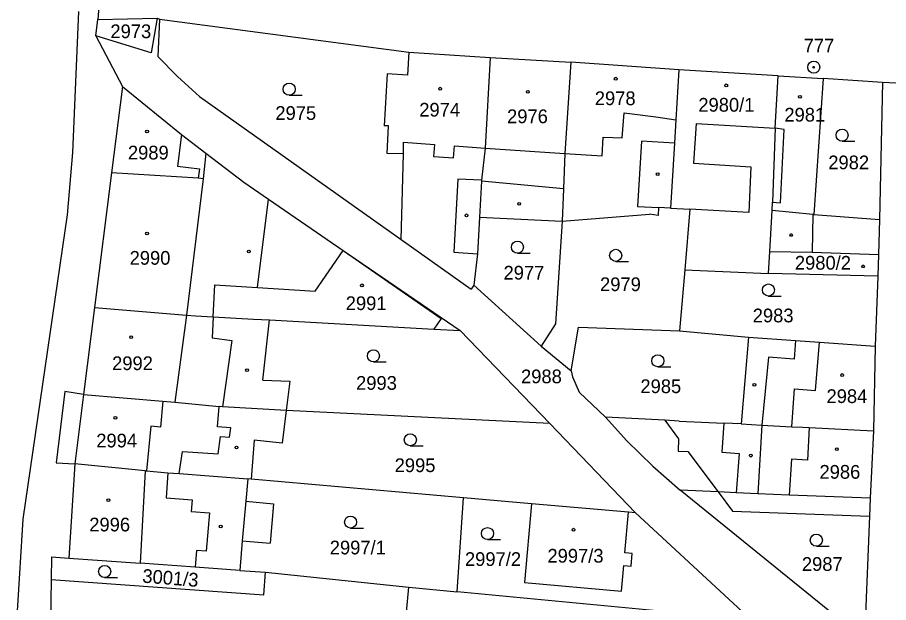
# Model space of a CAD drawing. Extents: x -755819 to -753140, y -1169796 to -1166000.
# Drawn here: x -754210.5 to -754102.6, y -1169066.6 to -1168994.1 of the extents above; entities that cross this region are included whole.
import ezdxf

# ---------------------------------------------------------------- set-up
doc = ezdxf.new("R2010")
doc.units = 0
for name, color, linetype in [('Vrstva 1', 7, 'Continuous'), ('Vrstva 17', 7, 'Continuous'), ('Vrstva 18', 7, 'Continuous'), ('Vrstva 19', 7, 'Continuous'), ('Vrstva 24', 7, 'Continuous'), ('Vrstva 25', 7, 'Continuous'), ('Vrstva 4', 7, 'Continuous')]:
    doc.layers.add(name, color=color, linetype=linetype)

msp = doc.modelspace()

# ---------------------------------------------------------------- linework, layer by layer
at = {"layer": 'Vrstva 1'}
for p, q in [((-754199.65, -1168981.56), (-754200.57, -1168994.32)), ((-754203.67, -1169010.81), (-754202.95, -1168993.33)), ((-754200.83, -1168996.33), (-754200.57, -1168994.32)), ((-754200.57, -1168994.32), (-754193.23, -1168994.15)), ((-754193.23, -1168994.15), (-754193.97, -1168998.42)), ((-754193.23, -1168994.15), (-754192.93, -1168994.25)), ((-754192.93, -1168994.25), (-754193.14, -1168998.89)), ((-754192.93, -1168994.25), (-754162.03, -1168998.34)), ((-754193.97, -1168998.42), (-754200.83, -1168996.33)), ((-754200.83, -1168996.33), (-754197.53, -1169002.63)), ((-754162.03, -1168998.34), (-754162.21, -1169001.2)), ((-754162.03, -1168998.34), (-754151.95, -1168999.03)), ((-754193.14, -1168998.89), (-754190.69, -1169001.38)), ((-754151.95, -1168999.03), (-754152.6, -1169010.26)), ((-754151.95, -1168999.03), (-754141.96, -1168999.6)), ((-754141.96, -1168999.6), (-754142.72, -1169010.93)), ((-754128.58, -1169000.55), (-754141.96, -1168999.6)), ((-754190.69, -1169001.38), (-754187.96, -1169003.85)), ((-754164.74, -1169001.06), (-754165.1, -1169007.47)), ((-754162.21, -1169001.2), (-754164.74, -1169001.06)), ((-754128.58, -1169000.55), (-754128.95, -1169006.76)), ((-754116.28, -1169001.27), (-754128.58, -1169000.55)), ((-754116.66, -1169007.79), (-754116.28, -1169001.27)), ((-754116.28, -1169001.27), (-754110.7, -1169001.6)), ((-754197.53, -1169002.63), (-754198.87, -1169013.3)), ((-754197.53, -1169002.63), (-754190.21, -1169008.55)), ((-754110.7, -1169001.6), (-754111.85, -1169018.49)), ((-754103.34, -1169002.11), (-754110.7, -1169001.6)), ((-754103.34, -1169002.11), (-754103.73, -1169019.08)), ((-754093.04, -1169002.69), (-754103.34, -1169002.11)), ((-754187.96, -1169003.85), (-754162.98, -1169021.58)), ((-754128.95, -1169006.76), (-754129.12, -1169009.63)), ((-754164.55, -1169007.5), (-754165.1, -1169007.47)), ((-754164.72, -1169010.92), (-754164.55, -1169007.5)), ((-754116.66, -1169007.79), (-754116.97, -1169016.96)), ((-754190.21, -1169008.55), (-754187.19, -1169010.87)), ((-754129.12, -1169009.63), (-754129.61, -1169017.68)), ((-754204.35, -1169018.52), (-754203.67, -1169010.81)), ((-754187.19, -1169010.87), (-754187.52, -1169014.04)), ((-754187.19, -1169010.87), (-754182.5, -1169014.48)), ((-754162.72, -1169010.97), (-754164.72, -1169010.92)), ((-754162.98, -1169021.58), (-754162.72, -1169010.97)), ((-754152.6, -1169010.26), (-754153.03, -1169014.22)), ((-754142.72, -1169010.93), (-754142.89, -1169015.28)), ((-754198.87, -1169013.3), (-754201.01, -1169029.98)), ((-754188.13, -1169013.98), (-754198.87, -1169013.3)), ((-754187.52, -1169014.04), (-754188.13, -1169013.98)), ((-754182.5, -1169014.48), (-754179.42, -1169016.59)), ((-754153.04, -1169014.33), (-754153.28, -1169018.81)), ((-754153.03, -1169014.22), (-754153.04, -1169014.33)), ((-754142.89, -1169015.28), (-754143.05, -1169019.32)), ((-754180.8, -1169027.54), (-754179.42, -1169016.59)), ((-754179.42, -1169016.59), (-754170.17, -1169022.93)), ((-754131.1, -1169017.6), (-754131.15, -1169018.59)), ((-754129.61, -1169017.68), (-754131.1, -1169017.6)), ((-754129.61, -1169017.68), (-754127.22, -1169017.81)), ((-754117.02, -1169017.96), (-754116.97, -1169016.96)), ((-754209.82, -1169056.23), (-754204.35, -1169018.52)), ((-754153.28, -1169018.81), (-754153.52, -1169023.33)), ((-754153.28, -1169018.81), (-754143.05, -1169019.32)), ((-754143.05, -1169019.32), (-754132.23, -1169018.43)), ((-754131.15, -1169018.59), (-754132.23, -1169018.43)), ((-754127.22, -1169017.81), (-754127.86, -1169025.32)), ((-754117.3, -1169023.07), (-754117.02, -1169017.96)), ((-754111.97, -1169018.48), (-754117.02, -1169017.96)), ((-754111.85, -1169018.49), (-754111.97, -1169018.48)), ((-754111.85, -1169018.49), (-754103.73, -1169019.08)), ((-754143.05, -1169019.32), (-754143.87, -1169032.04)), ((-754103.73, -1169019.08), (-754103.83, -1169023.43)), ((-754162.98, -1169021.58), (-754154.31, -1169027.72)), ((-754170.17, -1169022.93), (-754155.67, -1169032.87)), ((-754117.47, -1169025.79), (-754117.3, -1169023.07)), ((-754153.52, -1169023.33), (-754153.99, -1169027.25)), ((-754103.83, -1169023.43), (-754103.93, -1169026.12)), ((-754127.86, -1169025.32), (-754128.5, -1169032.89)), ((-754127.86, -1169025.32), (-754117.47, -1169025.79)), ((-754103.93, -1169026.12), (-754117.47, -1169025.79)), ((-754103.93, -1169026.12), (-754104.27, -1169034.81)), ((-754186.28, -1169031.15), (-754186.06, -1169027.21)), ((-754186.06, -1169027.21), (-754180.8, -1169027.54)), ((-754153.99, -1169027.25), (-754154.31, -1169027.72)), ((-754145.63, -1169034.78), (-754153.99, -1169027.25)), ((-754201.01, -1169029.98), (-754202.36, -1169040.77)), ((-754201.01, -1169029.98), (-754189.6, -1169030.97)), ((-754189.6, -1169030.97), (-754188.48, -1169031.03)), ((-754188.48, -1169031.03), (-754186.28, -1169031.15)), ((-754186.28, -1169031.15), (-754181.29, -1169031.43)), ((-754181.29, -1169031.43), (-754179.3, -1169031.54)), ((-754180.13, -1169039), (-754179.3, -1169031.54)), ((-754179.3, -1169031.54), (-754158.93, -1169032.69)), ((-754158.93, -1169032.69), (-754155.67, -1169032.87)), ((-754155.67, -1169032.87), (-754144.58, -1169044.37)), ((-754143.87, -1169032.04), (-754145.63, -1169034.78)), ((-754141.91, -1169037.85), (-754141.03, -1169032.42)), ((-754141.03, -1169032.42), (-754128.5, -1169032.89)), ((-754128.5, -1169032.89), (-754119.96, -1169033.67)), ((-754119.96, -1169033.67), (-754120.88, -1169044.43)), ((-754119.96, -1169033.67), (-754114.14, -1169034.09)), ((-754145.63, -1169034.78), (-754141.91, -1169037.85)), ((-754114.14, -1169034.09), (-754111.16, -1169034.31)), ((-754111.16, -1169034.31), (-754104.27, -1169034.81)), ((-754104.27, -1169034.81), (-754104.47, -1169045.3)), ((-754141.91, -1169037.85), (-754141.78, -1169038.59)), ((-754180.13, -1169039), (-754176.79, -1169039.13)), ((-754176.79, -1169039.13), (-754177.24, -1169042.75)), ((-754141.78, -1169038.59), (-754140.93, -1169040.5)), ((-754204.68, -1169040.4), (-754205.73, -1169049.26)), ((-754202.36, -1169040.77), (-754204.68, -1169040.4)), ((-754202.36, -1169040.77), (-754192.52, -1169041.61)), ((-754140.93, -1169040.5), (-754137.66, -1169043.58)), ((-754192.52, -1169041.61), (-754191.05, -1169041.73)), ((-754191.05, -1169041.73), (-754185.54, -1169042.29)), ((-754185.14, -1169042.31), (-754185.54, -1169042.29)), ((-754177.24, -1169042.75), (-754185.14, -1169042.31)), ((-754177.24, -1169042.75), (-754177.75, -1169046.82)), ((-754144.58, -1169044.37), (-754177.24, -1169042.75)), ((-754137.66, -1169043.58), (-754135.01, -1169046.51)), ((-754130.34, -1169043.98), (-754137.66, -1169043.58)), ((-754144.58, -1169044.37), (-754133.97, -1169055.46)), ((-754128.56, -1169044.08), (-754130.34, -1169043.98)), ((-754130.34, -1169043.98), (-754128.62, -1169046.28)), ((-754128.56, -1169044.08), (-754123.03, -1169044.33)), ((-754120.88, -1169044.43), (-754123.03, -1169044.33)), ((-754120.88, -1169044.43), (-754118.31, -1169044.57)), ((-754118.31, -1169044.57), (-754114.59, -1169044.77)), ((-754114.59, -1169044.77), (-754113.22, -1169044.84)), ((-754113.22, -1169044.84), (-754112.42, -1169044.88)), ((-754112.42, -1169044.88), (-754104.47, -1169045.3)), ((-754104.47, -1169045.3), (-754104.89, -1169053.62)), ((-754181.22, -1169046.43), (-754181.56, -1169051.26)), ((-754177.75, -1169046.82), (-754181.22, -1169046.43)), ((-754135.01, -1169046.51), (-754131.79, -1169049.65)), ((-754128.62, -1169046.28), (-754128.66, -1169047.8)), ((-754128.66, -1169047.8), (-754127.47, -1169047.84)), ((-754127.47, -1169047.84), (-754123.72, -1169052.86)), ((-754205.73, -1169049.26), (-754203.43, -1169049.39)), ((-754203.43, -1169049.39), (-754204.16, -1169061.05)), ((-754194.7, -1169050.25), (-754203.43, -1169049.39)), ((-754131.79, -1169049.65), (-754128.41, -1169052.62)), ((-754194.7, -1169050.25), (-754194.55, -1169050.26)), ((-754194.55, -1169050.26), (-754191.91, -1169050.47)), ((-754191.91, -1169050.47), (-754190.49, -1169050.58)), ((-754190.49, -1169050.58), (-754182.01, -1169051.25)), ((-754182.01, -1169051.25), (-754182.25, -1169054.02)), ((-754181.56, -1169051.26), (-754182.01, -1169051.25)), ((-754155.28, -1169053.58), (-754181.56, -1169051.26)), ((-754105.59, -1169071.13), (-754128.41, -1169052.62)), ((-754123.72, -1169052.86), (-754121.95, -1169055.24)), ((-754182.25, -1169054.02), (-754182.68, -1169058.92)), ((-754156.04, -1169065.25), (-754155.28, -1169053.58)), ((-754146.84, -1169054.32), (-754155.28, -1169053.58)), ((-754146.84, -1169054.32), (-754147.7, -1169064.07)), ((-754134.82, -1169055.38), (-754146.84, -1169054.32)), ((-754104.89, -1169053.62), (-754104.98, -1169055.87)), ((-754135.27, -1169060.41), (-754134.82, -1169055.38)), ((-754133.97, -1169055.46), (-754134.82, -1169055.38)), ((-754133.97, -1169055.46), (-754119.63, -1169068.71)), ((-754121.95, -1169055.24), (-754104.98, -1169055.87)), ((-754210.54, -1169067.62), (-754209.82, -1169056.23)), ((-754104.98, -1169055.87), (-754105.59, -1169071.13)), ((-754182.68, -1169058.92), (-754182.99, -1169062.58)), ((-754206.33, -1169060.89), (-754206.37, -1169063.72)), ((-754206.33, -1169060.89), (-754204.16, -1169061.05)), ((-754134.35, -1169060.5), (-754135.27, -1169060.41)), ((-754134.5, -1169062.05), (-754134.35, -1169060.5)), ((-754204.16, -1169061.05), (-754195.32, -1169061.69)), ((-754188.51, -1169062.18), (-754195.32, -1169061.69)), ((-754135.69, -1169065.16), (-754135.41, -1169061.97)), ((-754135.41, -1169061.97), (-754134.5, -1169062.05)), ((-754182.99, -1169062.58), (-754188.51, -1169062.18)), ((-754182.99, -1169062.58), (-754179.79, -1169062.81)), ((-754179.99, -1169065.61), (-754179.79, -1169062.81)), ((-754179.79, -1169062.81), (-754162.06, -1169064.68)), ((-754206.37, -1169063.72), (-754206.63, -1169082.04)), ((-754206.37, -1169063.72), (-754179.99, -1169065.61)), ((-754147.7, -1169064.07), (-754135.69, -1169065.16)), ((-754163.05, -1169076), (-754162.06, -1169064.68)), ((-754162.06, -1169064.68), (-754156.04, -1169065.25)), ((-754119.63, -1169068.71), (-754156.04, -1169065.25))]:
    msp.add_line(p, q, dxfattribs=at)
at = {"layer": 'Vrstva 24'}
for radius in [0.75, 0.1]:
    msp.add_circle((-754111.87, -1169000.22), radius, dxfattribs=at)
at = {"layer": 'Vrstva 25'}
for p, q in [((-754176.87, -1169003.69), (-754175.27, -1169003.69)), ((-754108.36, -1169009.4), (-754106.76, -1169009.4)), ((-754148.59, -1169023.27), (-754146.99, -1169023.27)), ((-754136.41, -1169024.29), (-754134.81, -1169024.29)), ((-754117.49, -1169028.58), (-754115.89, -1169028.58)), ((-754166.43, -1169036.74), (-754164.83, -1169036.74)), ((-754131.19, -1169037.35), (-754129.59, -1169037.35)), ((-754161.86, -1169047.14), (-754160.26, -1169047.14)), ((-754169.26, -1169057.34), (-754167.66, -1169057.34)), ((-754152.29, -1169058.77), (-754150.69, -1169058.77)), ((-754111.55, -1169059.59), (-754109.95, -1169059.59)), ((-754199.73, -1169063.47), (-754198.13, -1169063.47))]:
    msp.add_line(p, q, dxfattribs=at)
for points in [[(-754114.58, -1169020.88), (-754114.49, -1169021.03), (-754114.58, -1169021.18), (-754114.76, -1169021.18), (-754114.85, -1169021.03), (-754114.76, -1169020.88)], [(-754105.66, -1169024.76), (-754105.57, -1169024.91), (-754105.66, -1169025.06), (-754105.84, -1169025.06), (-754105.93, -1169024.91), (-754105.84, -1169024.76)]]:
    msp.add_lwpolyline(points, close=True, dxfattribs=at)
for centre, radius in [((-754136.41, -1169001.65), 0.175), ((-754176.87, -1169002.94), 0.75), ((-754122.71, -1169002.47), 0.175), ((-754158.16, -1169002.88), 0.175), ((-754147.29, -1169003.28), 0.175), ((-754113.58, -1169003.9), 0.175), ((-754194.48, -1169008.18), 0.175), ((-754108.36, -1169008.65), 0.75), ((-754131.21, -1169013.47), 0.175), ((-754148.38, -1169017.16), 0.175), ((-754154.9, -1169018.58), 0.175), ((-754194.48, -1169020.83), 0.175), ((-754148.59, -1169022.52), 0.75), ((-754181.87, -1169023.07), 0.175), ((-754136.41, -1169023.54), 0.75), ((-754167.85, -1169027.26), 0.175), ((-754117.49, -1169027.83), 0.75), ((-754196.44, -1169033.68), 0.175), ((-754166.43, -1169035.99), 0.75), ((-754131.19, -1169036.6), 0.75), ((-754182.09, -1169037.76), 0.175), ((-754108.36, -1169038.37), 0.175), ((-754119.23, -1169039.59), 0.175), ((-754198.4, -1169043.67), 0.175), ((-754161.86, -1169046.39), 0.75), ((-754183.39, -1169047.34), 0.175), ((-754109.01, -1169047.55), 0.175), ((-754119.67, -1169048.36), 0.175), ((-754199.27, -1169053.87), 0.175), ((-754169.26, -1169056.59), 0.75), ((-754185.35, -1169057.14), 0.175), ((-754152.29, -1169058.02), 0.75), ((-754141.63, -1169057.54), 0.175), ((-754111.55, -1169058.84), 0.75), ((-754199.73, -1169062.72), 0.75)]:
    msp.add_circle(centre, radius, dxfattribs=at)
at = {"layer": 'Vrstva 4'}
for p, q in [((-754135.59, -1169008.96), (-754135.37, -1169005.88)), ((-754135.37, -1169005.88), (-754134.35, -1169006)), ((-754134.35, -1169006), (-754131.45, -1169006.35)), ((-754131.45, -1169006.35), (-754128.95, -1169006.76)), ((-754126.43, -1169007.18), (-754126.77, -1169012.13)), ((-754126.43, -1169007.18), (-754116.66, -1169007.79)), ((-754115.55, -1169007.93), (-754116.66, -1169007.79)), ((-754115.98, -1169017.01), (-754115.55, -1169007.93)), ((-754190.21, -1169008.55), (-754190.7, -1169012.48)), ((-754138.09, -1169011.19), (-754137.96, -1169008.87)), ((-754137.96, -1169008.87), (-754135.59, -1169008.96)), ((-754162.72, -1169010.97), (-754162.69, -1169009.5)), ((-754162.69, -1169009.5), (-754158.88, -1169009.79)), ((-754158.88, -1169009.79), (-754158.99, -1169011.27)), ((-754156.51, -1169011.45), (-754156.4, -1169009.98)), ((-754156.4, -1169009.98), (-754152.6, -1169010.26)), ((-754133.2, -1169009.37), (-754133.71, -1169017.47)), ((-754129.12, -1169009.63), (-754133.2, -1169009.37)), ((-754158.99, -1169011.27), (-754156.51, -1169011.45)), ((-754152.6, -1169010.26), (-754142.72, -1169010.93)), ((-754142.72, -1169010.93), (-754138.09, -1169011.19)), ((-754126.77, -1169012.13), (-754119.66, -1169012.55)), ((-754190.7, -1169012.48), (-754187.98, -1169012.82)), ((-754187.98, -1169012.82), (-754188.13, -1169013.98)), ((-754119.66, -1169012.55), (-754119.91, -1169018.22)), ((-754187.52, -1169014.04), (-754189.6, -1169030.97)), ((-754155.97, -1169014.08), (-754156.46, -1169023.16)), ((-754153.03, -1169014.22), (-754155.97, -1169014.08)), ((-754142.89, -1169015.28), (-754153.04, -1169014.33)), ((-754133.71, -1169017.47), (-754131.1, -1169017.6)), ((-754116.97, -1169016.96), (-754115.98, -1169017.01)), ((-754119.91, -1169018.22), (-754127.22, -1169017.81)), ((-754111.97, -1169018.48), (-754112.05, -1169023.16)), ((-754173.66, -1169027.99), (-754170.17, -1169022.93)), ((-754170.17, -1169022.93), (-754158.05, -1169031.36)), ((-754156.46, -1169023.16), (-754153.52, -1169023.33)), ((-754117.3, -1169023.07), (-754112.05, -1169023.16)), ((-754112.05, -1169023.16), (-754103.83, -1169023.43)), ((-754180.8, -1169027.54), (-754173.66, -1169027.99)), ((-754189.6, -1169030.97), (-754191.05, -1169041.73)), ((-754186.28, -1169031.15), (-754186.42, -1169033.75)), ((-754158.05, -1169031.36), (-754158.93, -1169032.69)), ((-754186.42, -1169033.75), (-754183.98, -1169034.09)), ((-754183.98, -1169034.09), (-754185.14, -1169042.31)), ((-754114.14, -1169034.09), (-754114.3, -1169036.4)), ((-754111.65, -1169040.29), (-754111.16, -1169034.31)), ((-754117.46, -1169036.17), (-754118.31, -1169044.57)), ((-754114.3, -1169036.4), (-754117.46, -1169036.17)), ((-754114.59, -1169044.77), (-754114.26, -1169040.08)), ((-754114.26, -1169040.08), (-754111.65, -1169040.29)), ((-754202.36, -1169040.77), (-754203.43, -1169049.39)), ((-754192.52, -1169041.61), (-754192.82, -1169044.82)), ((-754185.73, -1169044.8), (-754185.54, -1169042.29)), ((-754194.02, -1169044.71), (-754194.55, -1169050.26)), ((-754192.82, -1169044.82), (-754194.02, -1169044.71)), ((-754123.03, -1169044.33), (-754123.28, -1169047.92)), ((-754118.31, -1169044.57), (-754118.81, -1169053.08)), ((-754184.08, -1169044.93), (-754185.73, -1169044.8)), ((-754184.28, -1169046.09), (-754184.08, -1169044.93)), ((-754112.42, -1169044.88), (-754112.65, -1169048.92)), ((-754185.67, -1169048.15), (-754185.36, -1169045.97)), ((-754185.36, -1169045.97), (-754184.28, -1169046.09)), ((-754190.49, -1169050.58), (-754190.1, -1169047.86)), ((-754190.1, -1169047.86), (-754185.67, -1169048.15)), ((-754123.28, -1169047.92), (-754121.13, -1169048.08)), ((-754121.13, -1169048.08), (-754121.48, -1169052.98)), ((-754114.64, -1169048.81), (-754114.9, -1169053.24)), ((-754112.65, -1169048.92), (-754114.64, -1169048.81)), ((-754194.7, -1169050.25), (-754195.32, -1169061.69)), ((-754191.91, -1169050.47), (-754192.1, -1169053.59)), ((-754123.72, -1169052.86), (-754128.41, -1169052.62)), ((-754121.48, -1169052.98), (-754123.72, -1169052.86)), ((-754118.81, -1169053.08), (-754121.48, -1169052.98)), ((-754114.9, -1169053.24), (-754118.81, -1169053.08)), ((-754104.89, -1169053.62), (-754114.9, -1169053.24)), ((-754192.1, -1169053.59), (-754188.89, -1169053.85)), ((-754188.89, -1169053.85), (-754189, -1169055.28)), ((-754182.25, -1169054.02), (-754178.81, -1169054.32)), ((-754178.81, -1169054.32), (-754179.21, -1169059.22)), ((-754189, -1169055.28), (-754186.75, -1169055.46)), ((-754186.75, -1169055.46), (-754187.16, -1169060.18)), ((-754182.68, -1169058.92), (-754179.21, -1169059.22)), ((-754188.35, -1169060.1), (-754188.51, -1169062.18)), ((-754187.16, -1169060.18), (-754188.35, -1169060.1))]:
    msp.add_line(p, q, dxfattribs=at)

# ---------------------------------------------------------------- texts
at = {"layer": 'Vrstva 17'}
msp.add_text('777', height=1.7, dxfattribs=at).set_placement((-754113.12, -1168998.39))
at = {"layer": 'Vrstva 18'}
for s, p in [('2973', (-754199.02, -1168996.62)), ('2975', (-754178.58, -1169006.75)), ('2982', (-754110.07, -1169012.87)), ('2977', (-754150.31, -1169026.54)), ('2979', (-754138.35, -1169027.97)), ('2983', (-754119.43, -1169031.84)), ('2988', (-754148.14, -1169039.39)), ('2993', (-754168.58, -1169040.2)), ('2985', (-754133.35, -1169040.61)), ('2995', (-754163.8, -1169050.4)), ('2997/1', (-754171.84, -1169060.6)), ('2997/2', (-754155.09, -1169062.03)), ('2987', (-754113.34, -1169062.64))]:
    msp.add_text(s, height=1.7, dxfattribs=at).set_placement(p)
msp.add_text('3001/3', height=1.7, rotation=355.5203, dxfattribs=at).set_placement((-754195.11, -1169064.09))
at = {"layer": 'Vrstva 19'}
for s, p in [('2978', (-754139, -1169004.92)), ('2974', (-754160.75, -1169006.34)), ('2980/1', (-754126.17, -1169005.73)), ('2976', (-754149.87, -1169007.16)), ('2981', (-754115.51, -1169006.96)), ('2989', (-754196.85, -1169011.65)), ('2990', (-754196.64, -1169024.7)), ('2980/2', (-754114.21, -1169025.31)), ('2991', (-754169.86, -1169030.32)), ('2992', (-754198.81, -1169037.76)), ('2984', (-754110.29, -1169041.84)), ('2994', (-754200.77, -1169047.34)), ('2986', (-754111.16, -1169051.22)), ('2996', (-754201.64, -1169057.75)), ('2997/3', (-754144.87, -1169061.62))]:
    msp.add_text(s, height=1.7, dxfattribs=at).set_placement(p)

doc.saveas('drawing.dxf')
